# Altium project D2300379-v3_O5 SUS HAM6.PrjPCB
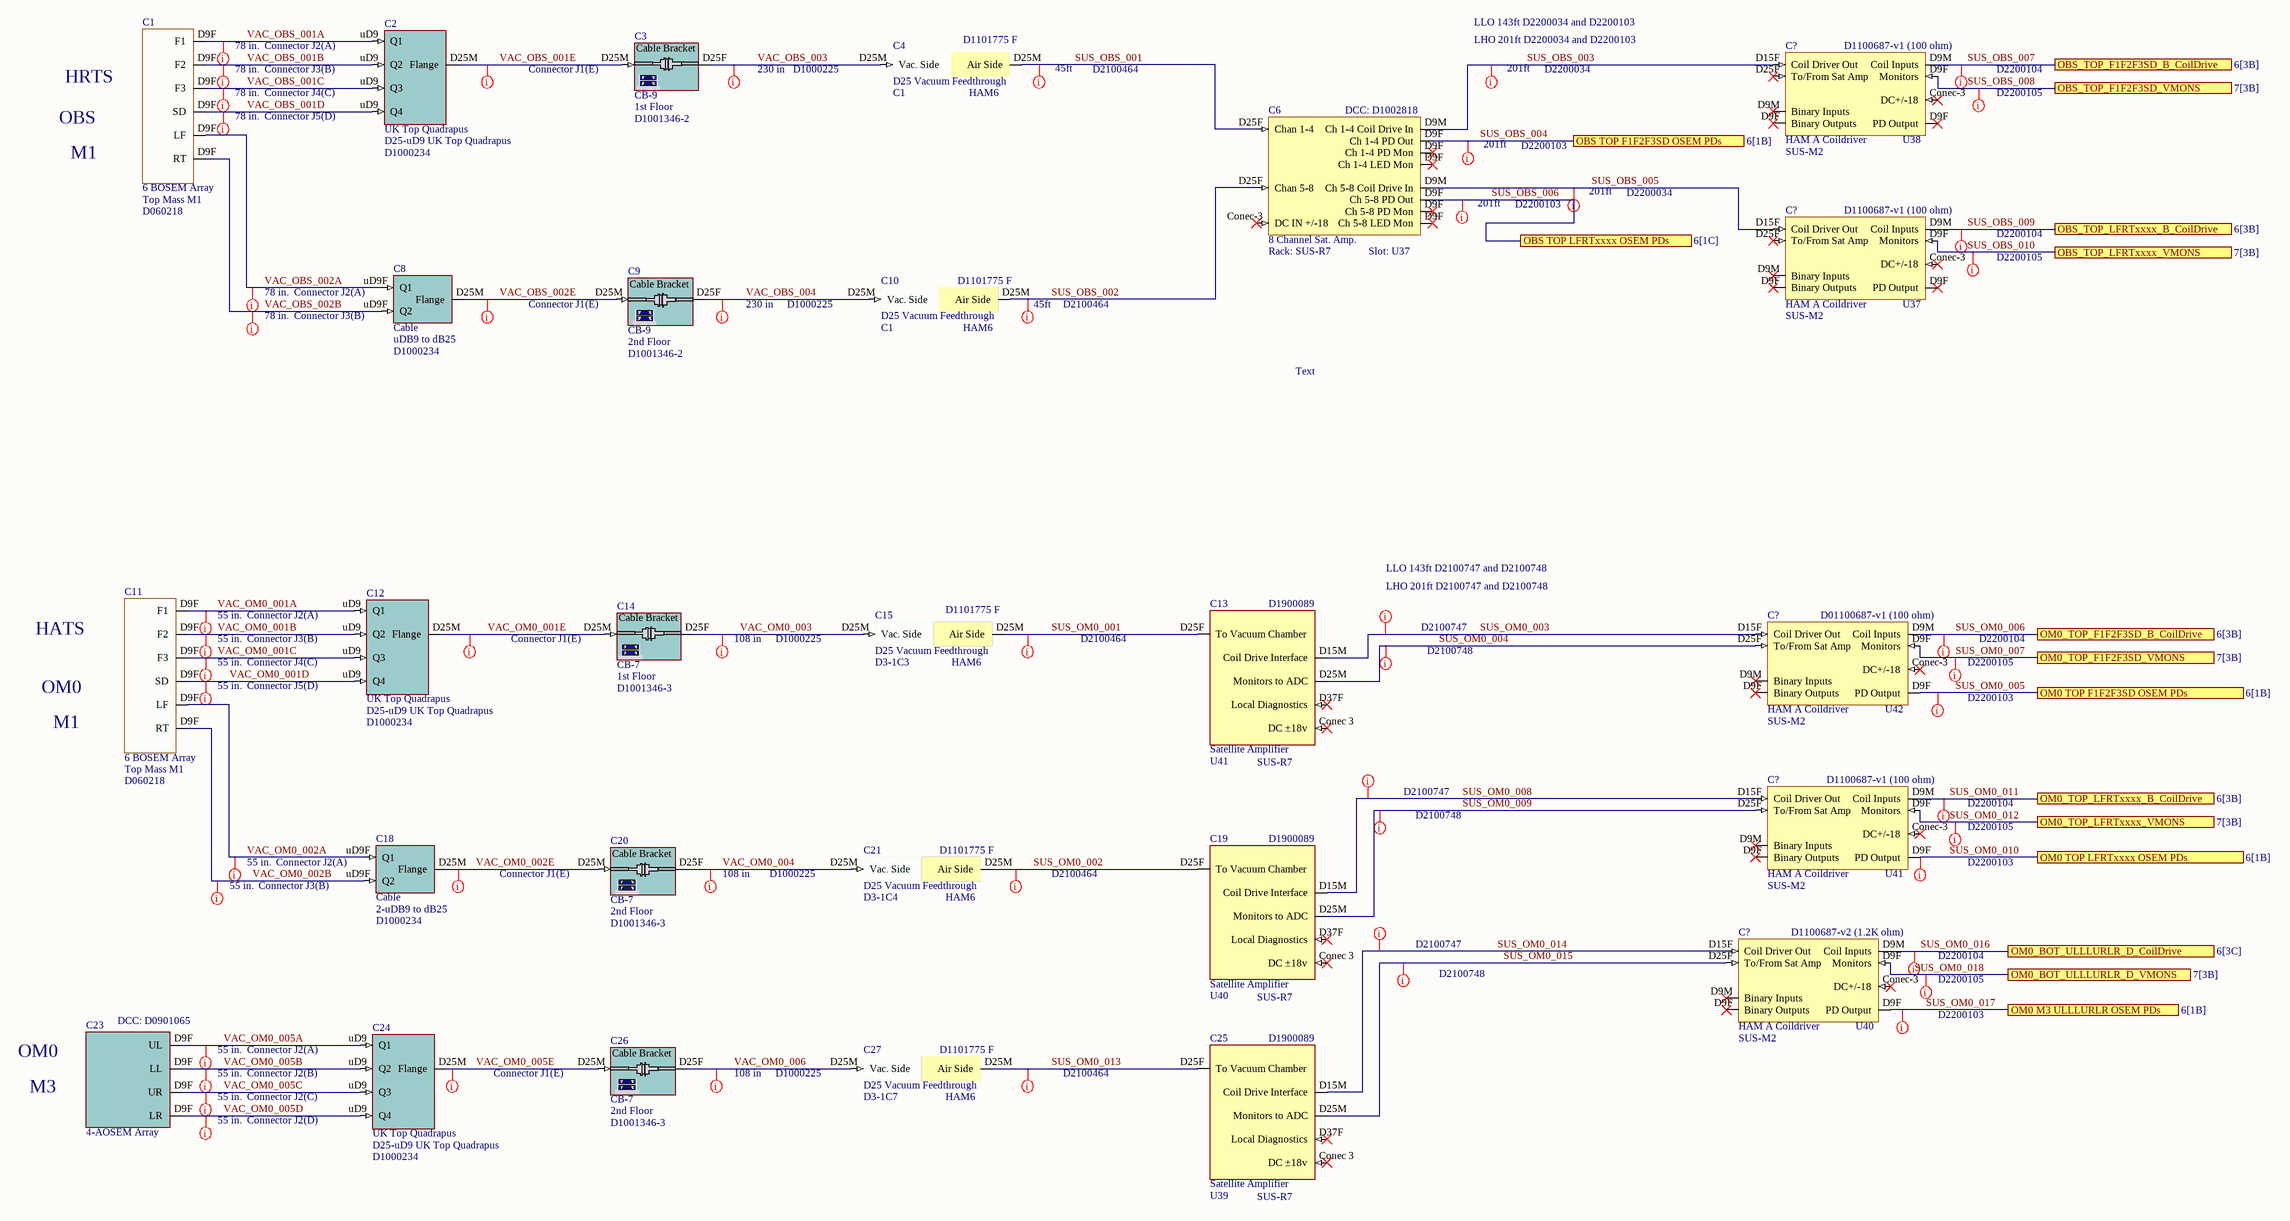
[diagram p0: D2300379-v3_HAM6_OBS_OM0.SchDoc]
5 sheets, 65 parts. Net scope: flat (ports and power ports of the same name join across sheets).
Sheets:
  D2300379-v3_HAM6_OBS_OM0.SchDoc
  D2300379-v3_HAM6_OMA1_OMB1.SchDoc
  D2300379-v1_SUS_HAM6_ADC_DAC.SchDoc
  D2300379-v1_SUSAUXH6_ADC_DAC.SchDoc
  D2300379-v1_RACK_SUS_R7.SchDoc

## Sheet D2300379-v3_HAM6_OBS_OM0.SchDoc: HAM6 OBS OM0
size C; Engineer: L. Sanchez; Organization: LIGO Laboratory; Address1: California Institute of Technology; Address2: Massachusetts Institute of Technology; DocumentNumber: D2300379; Revision: v2; SheetNumber: 1; SheetTotal: 9

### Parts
(Parts that share a designator on the sheet are numbered #1, #2 ... from top to bottom, then left to right.)
C1  6 BOSEM Array  Parameter: Top Mass M1  DCC: D060218
C2  UK Top Quadrapus  Parameter: D25-uD9 UK Top Quadrapus  DCC: D1000234
C3  Rack: CB-9  Slot: 1st Floor  DCC: D1001346-2  (hidden comment: Cable Bracket)
C4  D25 Vacuum Feedthrough  value C1  DCC: D1101775 F  Chamber: HAM6
C6  8 Channel Sat. Amp.  DCC: D1002818  Rack: SUS-R7  Slot: U37
C8  Cable  value uDB9 to dB25  DCC: D1000234
C9  Rack: CB-9  Slot: 2nd Floor  DCC: D1001346-2  (hidden comment: Cable Bracket)
C10  D25 Vacuum Feedthrough  value C1  DCC: D1101775 F  Chamber: HAM6
C11  6 BOSEM Array  Parameter: Top Mass M1  DCC: D060218
C12  UK Top Quadrapus  Parameter: D25-uD9 UK Top Quadrapus  DCC: D1000234
C13  Satellite Amplifier  Slot: U41  Rack: SUS-R7  DCC: D1900089
C14  Rack: CB-7  Slot: 1st Floor  DCC: D1001346-3  (hidden comment: Cable Bracket)
C15  D25 Vacuum Feedthrough  value D3-1C3  DCC: D1101775 F  Chamber: HAM6
C18  Cable  value 2-uDB9 to dB25  DCC: D1000234
C19  Satellite Amplifier  Slot: U40  Rack: SUS-R7  DCC: D1900089
C20  Rack: CB-7  Slot: 2nd Floor  DCC: D1001346-3  (hidden comment: Cable Bracket)
C21  D25 Vacuum Feedthrough  value D3-1C4  DCC: D1101775 F  Chamber: HAM6
C23  4-AOSEM Array  DCC: D0901065
C24  UK Top Quadrapus  Parameter: D25-uD9 UK Top Quadrapus  DCC: D1000234
C25  Satellite Amplifier  Slot: U39  Rack: SUS-R7  DCC: D1900089
C26  Rack: CB-7  Slot: 2nd Floor  DCC: D1001346-3  (hidden comment: Cable Bracket)
C27  D25 Vacuum Feedthrough  value D3-1C7  DCC: D1101775 F  Chamber: HAM6
C?#1  HAM A Coildriver
C?#2  HAM A Coildriver
C?#3  HAM A Coildriver
C?#4  HAM A Coildriver
C?#5  HAM A Coildriver

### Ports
OBS TOP F1F2F3SD OSEM PDs (see 6[1B]), OBS TOP LFRTxxxx OSEM PDs (see 6[1C]), OBS_TOP_F1F2F3SD_B_CoilDrive (see 6[3B]), OBS_TOP_F1F2F3SD_VMONS (see 7[3B]), OBS_TOP_LFRTxxxx_B_CoilDrive (see 6[3B]), OBS_TOP_LFRTxxxx_VMONS (see 7[3B]), OM0 M3 ULLLURLR OSEM PDs (see 6[1B]), OM0 TOP F1F2F3SD OSEM PDs (see 6[1B]), OM0 TOP LFRTxxxx OSEM PDs (see 6[1B]), OM0_BOT_ULLLURLR_D_CoilDrive (see 6[3C]), OM0_BOT_ULLLURLR_D_VMONS (see 7[3B]), OM0_TOP_F1F2F3SD_B_CoilDrive (see 6[3B]), OM0_TOP_F1F2F3SD_VMONS (see 7[3B]), OM0_TOP_LFRTxxxx_B_CoilDrive (see 6[3B]), OM0_TOP_LFRTxxxx_VMONS (see 7[3B])

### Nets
SUS_OBS_001: C4.D25M(Air_Side) C6.D25F(Chan_1-4)
SUS_OBS_002: C6.D25F(Chan_5-8) C10.D25M(Air_Side)
SUS_OBS_003: C6.D9M(Ch_1-4_Coil_Drive_In) C?#1.D15F(Coil_Driver_Out)
SUS_OBS_004: C6.D9F(Ch_1-4_PD_Out) ; port OBS TOP F1F2F3SD OSEM PDs
SUS_OBS_005: C6.D9M(Ch_5-8_Coil_Drive_In) C?#2.D15F(Coil_Driver_Out)
SUS_OBS_006: C6.D9F(Ch_5-8_PD_Out) ; port OBS TOP LFRTxxxx OSEM PDs
SUS_OBS_007: C?#1.D9M(Coil_Inputs) ; port OBS_TOP_F1F2F3SD_B_CoilDrive
SUS_OBS_008: C?#1.D9F(PD_Output) ; port OBS_TOP_F1F2F3SD_VMONS
SUS_OBS_009: C?#2.D9M(Coil_Inputs) ; port OBS_TOP_LFRTxxxx_B_CoilDrive
SUS_OBS_010: C?#2.D9F(PD_Output) ; port OBS_TOP_LFRTxxxx_VMONS
SUS_OM0_001: C13.D25F(To_Vacuum_Chamber) C15.D25M(Air_Side)
SUS_OM0_002: C19.D25F(To_Vacuum_Chamber) C21.D25M(Air_Side)
SUS_OM0_003: C13.D15M(Coil_Drive_Interface) C?#3.D15F(Coil_Driver_Out)
SUS_OM0_004: C13.D25M(Monitors_to_ADC) C?#3.D25F(To/From_Sat_Amp)
SUS_OM0_005: C?#3.D9F(PD_Output) ; port OM0 TOP F1F2F3SD OSEM PDs
SUS_OM0_006: C?#3.D9M(Coil_Inputs) ; port OM0_TOP_F1F2F3SD_B_CoilDrive
SUS_OM0_007: C?#3.D9F(Monitors) ; port OM0_TOP_F1F2F3SD_VMONS
SUS_OM0_008: C19.D15M(Coil_Drive_Interface) C?#4.D15F(Coil_Driver_Out)
SUS_OM0_009: C19.D25M(Monitors_to_ADC) C?#4.D25F(To/From_Sat_Amp)
SUS_OM0_010: C?#4.D9F(PD_Output) ; port OM0 TOP LFRTxxxx OSEM PDs
SUS_OM0_011: C?#4.D9M(Coil_Inputs) ; port OM0_TOP_LFRTxxxx_B_CoilDrive
SUS_OM0_012: C?#4.D9F(Monitors) ; port OM0_TOP_LFRTxxxx_VMONS
SUS_OM0_013: C25.D25F(To_Vacuum_Chamber) C27.D25M(Air_Side)
SUS_OM0_014: C25.D15M(Coil_Drive_Interface) C?#5.D15F(Coil_Driver_Out)
SUS_OM0_015: C25.D25M(Monitors_to_ADC) C?#5.D25F(To/From_Sat_Amp)
SUS_OM0_016: C?#5.D9M(Coil_Inputs) ; port OM0_BOT_ULLLURLR_D_CoilDrive
SUS_OM0_017: C?#5.D9F(PD_Output) ; port OM0 M3 ULLLURLR OSEM PDs
SUS_OM0_018: C?#5.D9F(Monitors) ; port OM0_BOT_ULLLURLR_D_VMONS
VAC_OBS_001A: C1.D9F(F1) C2.uD9(Q1)
VAC_OBS_001B: C1.D9F(F2) C2.uD9(Q2)
VAC_OBS_001C: C1.D9F(F3) C2.uD9(Q3)
VAC_OBS_001D: C1.D9F(SD) C2.uD9(Q4)
VAC_OBS_001E: C2.D25M(Flange) C3.D25M
VAC_OBS_002A: C1.D9F(LF) C8.uD9F(Q1)
VAC_OBS_002B: C1.D9F(RT) C8.uD9F(Q2)
VAC_OBS_002E: C8.D25M(Flange) C9.D25M
VAC_OBS_003: C3.D25F C4.D25M(Vac._Side)
VAC_OBS_004: C9.D25F C10.D25M(Vac._Side)
VAC_OM0_001A: C11.D9F(F1) C12.uD9(Q1)
VAC_OM0_001B: C11.D9F(F2) C12.uD9(Q2)
VAC_OM0_001C: C11.D9F(F3) C12.uD9(Q3)
VAC_OM0_001D: C11.D9F(SD) C12.uD9(Q4)
VAC_OM0_001E: C12.D25M(Flange) C14.D25M
VAC_OM0_002A: C11.D9F(LF) C18.uD9F(Q1)
VAC_OM0_002B: C11.D9F(RT) C18.uD9F(Q2)
VAC_OM0_002E: C18.D25M(Flange) C20.D25M
VAC_OM0_003: C14.D25F C15.D25M(Vac._Side)
VAC_OM0_004: C20.D25F C21.D25M(Vac._Side)
VAC_OM0_005A: C23.D9F(UL) C24.uD9(Q1)
VAC_OM0_005B: C23.D9F(LL) C24.uD9(Q2)
VAC_OM0_005C: C23.D9F(UR) C24.uD9(Q3)
VAC_OM0_005D: C23.D9F(LR) C24.uD9(Q4)
VAC_OM0_005E: C24.D25M(Flange) C26.D25M
VAC_OM0_006: C26.D25F C27.D25M(Vac._Side)

Not connected (* = marked no-connect by the designer): C6 Conec-3(DC_IN_+/-18)*; C13 Conec 3(DC_±18v)* D37F(Local_Diagnostics)*; C19 Conec 3(DC_±18v)* D37F(Local_Diagnostics)*; C25 Conec 3(DC_±18v)* D37F(Local_Diagnostics)*; C?#1 Conec-3(DC+/-18)* D25F(To/From_Sat_Amp)*; C?#2 Conec-3(DC+/-18)* D25F(To/From_Sat_Amp)*; C?#3 Conec-3(DC+/-18)*; C?#4 Conec-3(DC+/-18)*; C?#5 Conec-3(DC+/-18)*

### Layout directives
DCC: D2200103: SUS_OM0_005, SUS_OM0_010, SUS_OM0_017
DCC: D2100748: SUS_OM0_004, SUS_OM0_009, SUS_OM0_015
DCC: D2100747: SUS_OM0_003, SUS_OM0_008, SUS_OM0_014
Length: 201ft; DCC: D2200034: SUS_OBS_003, SUS_OBS_005
Length: 201ft; DCC: D2200103: SUS_OBS_004, SUS_OBS_006
DCC: D2200104: SUS_OBS_007, SUS_OBS_009, SUS_OM0_006, SUS_OM0_011, SUS_OM0_016
DCC: D2200105: SUS_OBS_008, SUS_OBS_010, SUS_OM0_007, SUS_OM0_012, SUS_OM0_018
DCC: D1000225: VAC_OBS_003, VAC_OBS_004, VAC_OM0_003, VAC_OM0_004, VAC_OM0_006
DCC: D2100464: SUS_OM0_001, SUS_OM0_002, SUS_OM0_013
Length: 45ft; DCC: D2100464: SUS_OBS_001, SUS_OBS_002
DCC: Connector J2(A): VAC_OBS_001A, VAC_OBS_002A, VAC_OM0_001A, VAC_OM0_002A, VAC_OM0_005A
DCC: Connector J2(B): VAC_OM0_005B
DCC: Connector J2(C): VAC_OM0_005C
DCC: Connector J2(D): VAC_OM0_005D
DCC: Connector J1(E): VAC_OM0_005E
Length: 2.3ft; DCC: Connector J1(E): VAC_OBS_001E, VAC_OBS_002E, VAC_OM0_001E, VAC_OM0_002E
DCC: Connector J3(B): VAC_OBS_001B, VAC_OBS_002B, VAC_OM0_001B, VAC_OM0_002B
DCC: Connector J5(D): VAC_OBS_001D, VAC_OM0_001D
DCC: Connector J4(C): VAC_OBS_001C, VAC_OM0_001C

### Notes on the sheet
- (near C1) 78 in.
- LLO 143ft D2200034 and D2200103
- LHO 201ft D2200034 and D2200103
- (near C?#1) D1100687-v1 (100 ohm)
- HRTS
- 230 in
- OBS
- M1
- (near C?#1) SUS-M2
- (near C?#1) U38
- (near C?#2) D1100687-v1 (100 ohm)
- 78 in.
- (near C?#2) SUS-M2
- (near C?#2) U37
- Text
- LLO 143ft D2100747 and D2100748
- HATS
- (near C11) 55 in.
- 108 in
- LHO 201ft D2100747 and D2100748
- (near C?#3) D01100687-v1 (100 ohm)
- OM0
- (near C?#3) SUS-M2
- (near C?#3) U42
- (near C?#4) D1100687-v1 (100 ohm)
- 55 in.
- (near C?#4) U41
- (near C?#4) SUS-M2
- (near C?#5) D1100687-v2 (1.2K ohm)
- (near C?#5) SUS-M2
- (near C?#5) U40
- M3

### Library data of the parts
C1 C11 = BOSEM_BS_M1: BOSEM; Serial: Sxxxxxxx; System: SUS; Rack: R?; Slot: U?
C2 C12 C24 = D1000234 D25 Quadrapus: Slot: U?; Rack: R?; Serial: Sxxxxxxx; System: SUS
C3 C14 = D1001347-2 1st Cable Bracket: D1001347-2 1/2 Cable Bracket for BSC Tables; Serial: Sxxxxxxx; System: SUS
C4 C10 C15 C21 C27 = VacFeedD25: Serial: Sxxxxxxx; System: ISC; Rack: R?; Slot: U?
C6 = 8 Channel Sat. Amp.: Serial: Sxxxxxxx; System: ISC
C8 C18 = D2100050 D25 2-udB9: Rack: SUS-R?; Serial: Sxxxxxxx; Slot: U?; System: SUS
C9 C20 C26 = D1001347-2 2nd Cable Bracket: D1001347-2 2/2 Cable Bracket for BSC Tables; Serial: Sxxxxxxx; System: SUS
C13 C19 C25 = Satellite Amplifier D1900089: System: SUS; Serial: Sxxxxxxx
C23 = 4-BOSEM Array: Rack: SUS-R?; Serial: Sxxxxxxx; Slot: U?; System: SUS; Parameter: OM3 HAM6 M1
C?#1-C?#5 = CD HAM-A D1100687: Serial: Sxxxxxxx; System: ISC

## Sheet D2300379-v3_HAM6_OMA1_OMB1.SchDoc: HAM6 OMA1,OMB1 DITHERS SUS
size C; Engineer: L. Sanchez; Organization: LIGO Laboratory; Address1: California Institute of Technology; Address2: Massachusetts Institute of Technology; DocumentNumber: D2300379; Revision: v2; SheetNumber: 2; SheetTotal: 9
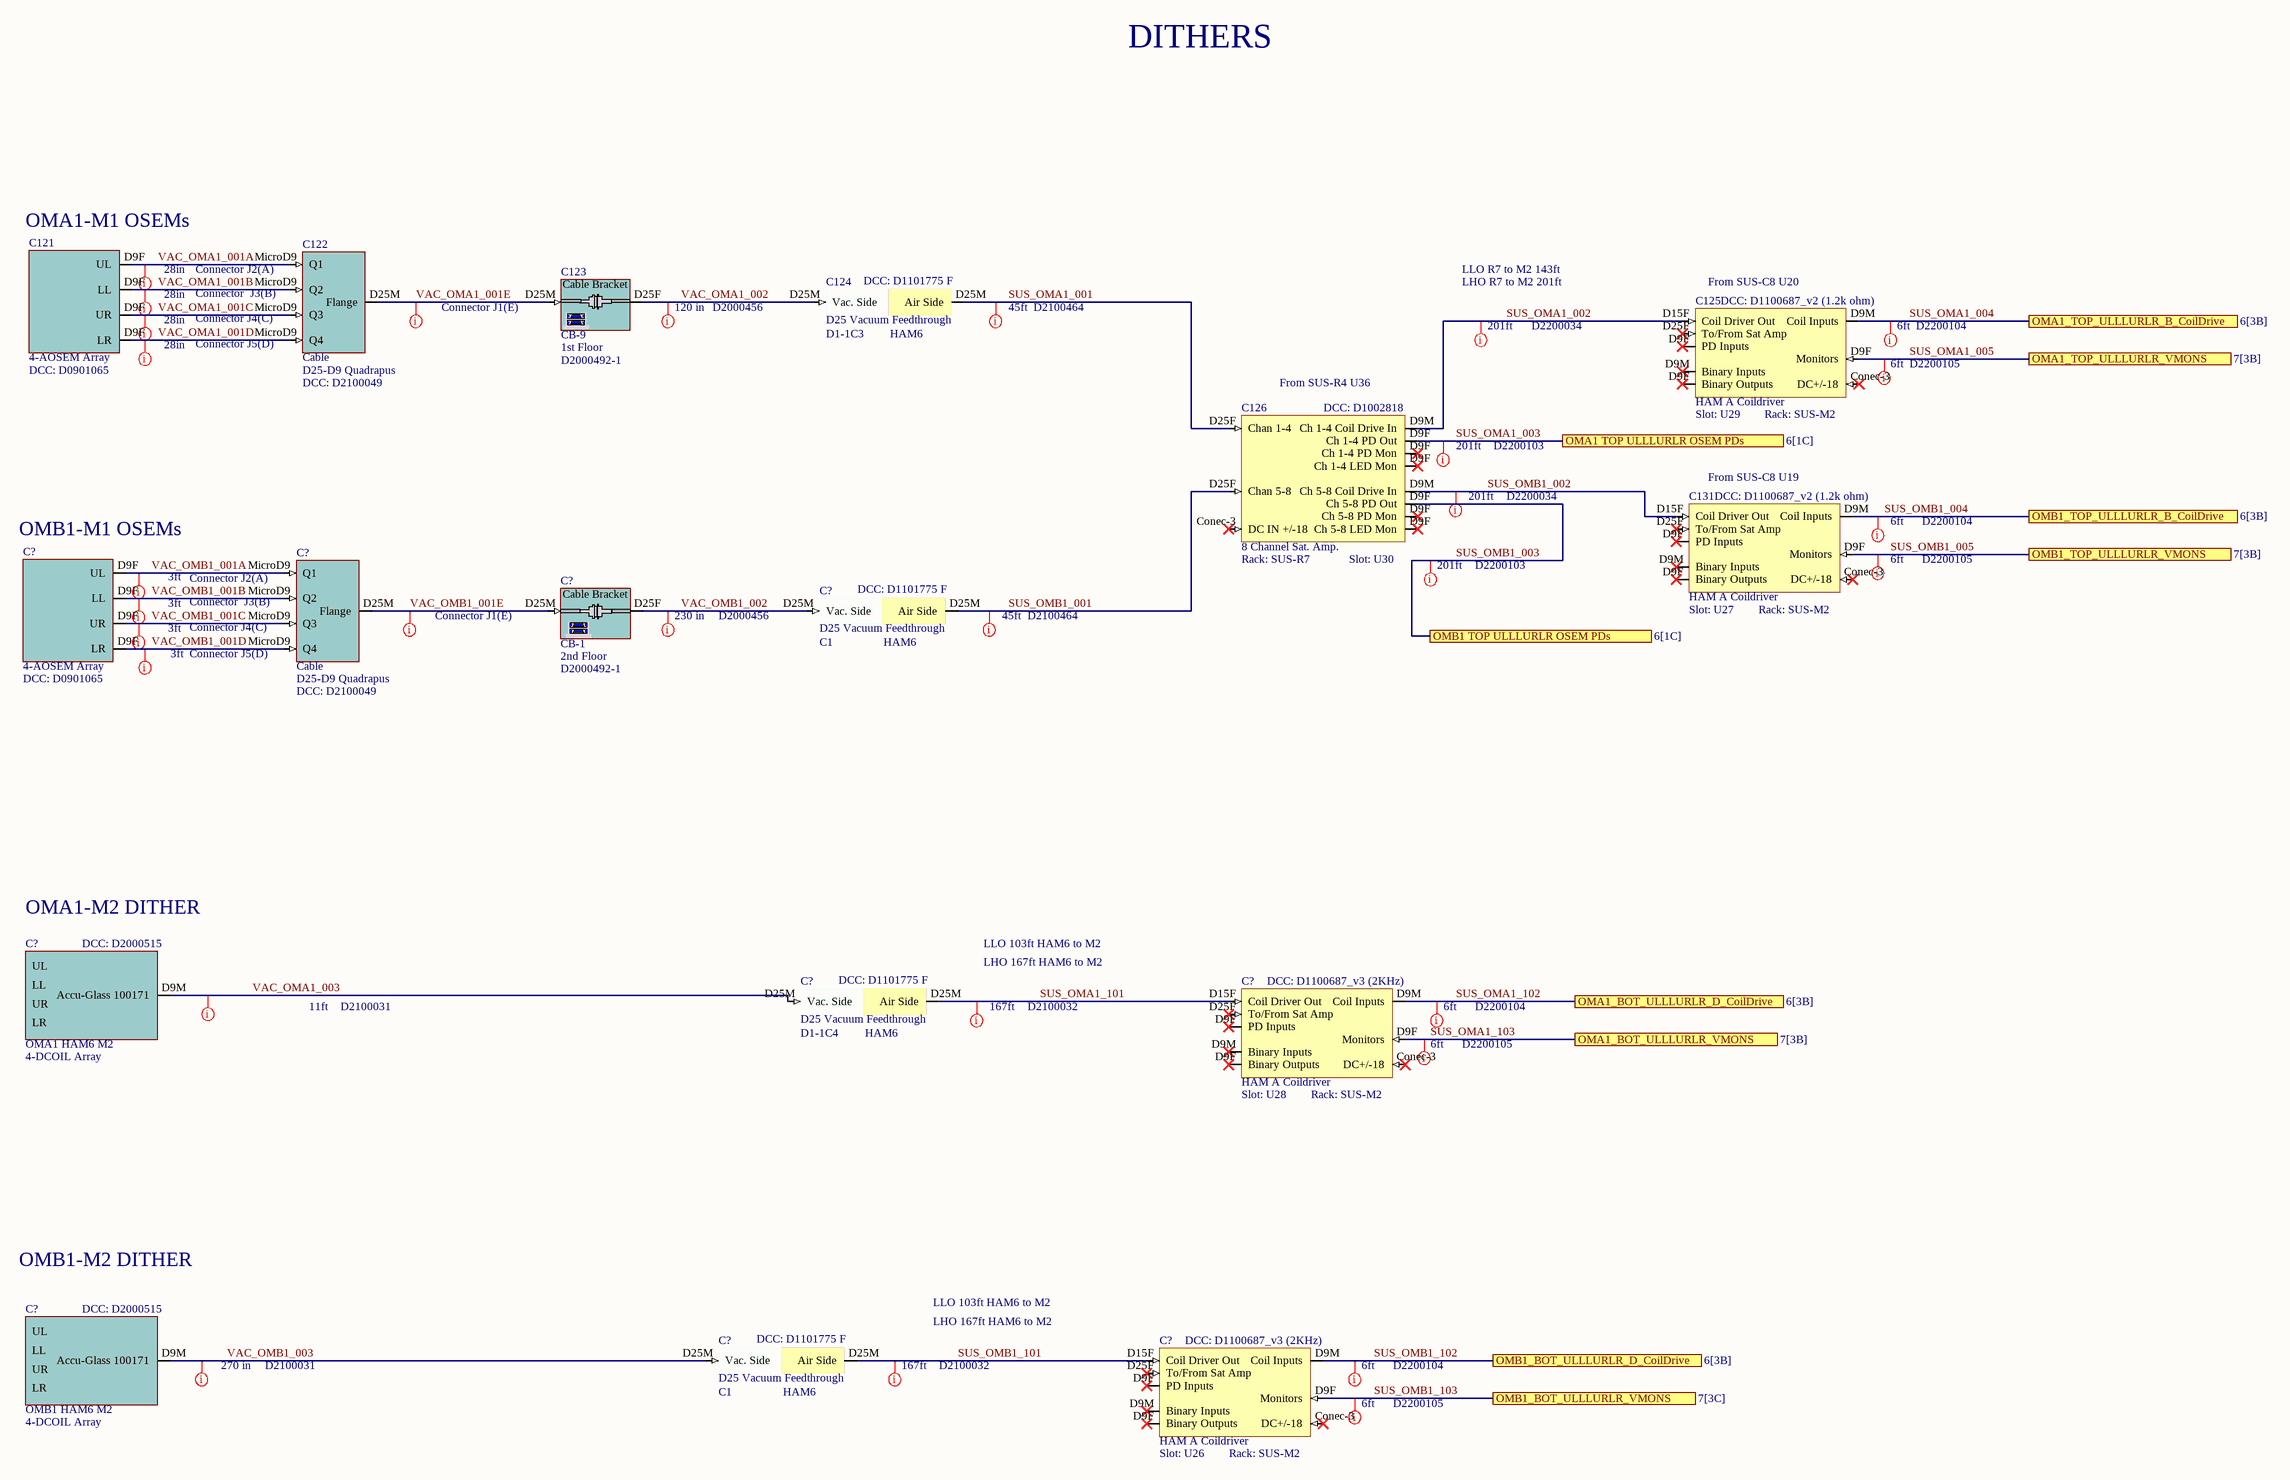
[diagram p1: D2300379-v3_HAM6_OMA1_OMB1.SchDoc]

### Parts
(Parts that share a designator on the sheet are numbered #1, #2 ... from top to bottom, then left to right.)
C121  4-AOSEM Array  DCC: D0901065
C122  Cable  value D25-D9 Quadrapus  DCC: D2100049
C123  Rack: CB-9  Slot: 1st Floor  DCC: D2000492-1  (hidden comment: Cable Bracket)
C124  D25 Vacuum Feedthrough  DCC: D1101775 F  Feedthrough: D1-1C3  Chamber: HAM6
C125  HAM A Coildriver  DCC: D1100687_v2 (1.2k ohm)  Rack: SUS-M2  Slot: U29
C126  8 Channel Sat. Amp.  DCC: D1002818  Rack: SUS-R7  Slot: U30
C131  HAM A Coildriver  DCC: D1100687_v2 (1.2k ohm)  Rack: SUS-M2  Slot: U27
C?#6  Rack: CB-1  Slot: 2nd Floor  DCC: D2000492-1  (hidden comment: Cable Bracket)
C?#7  D25 Vacuum Feedthrough  DCC: D1101775 F  Feedthrough: C1  Chamber: HAM6
C?#8  4-AOSEM Array  DCC: D0901065
C?#9  Cable  value D25-D9 Quadrapus  DCC: D2100049
C?#10  value 4-DCOIL Array  Rack: OMA1 HAM6 M2  DCC: D2000515  (hidden comment: Cable)
C?#11  D25 Vacuum Feedthrough  DCC: D1101775 F  Feedthrough: D1-1C4  Chamber: HAM6
C?#12  HAM A Coildriver  DCC: D1100687_v3 (2KHz)  Rack: SUS-M2  Slot: U28
C?#13  value 4-DCOIL Array  Rack: OMB1 HAM6 M2  DCC: D2000515  (hidden comment: Cable)
C?#14  D25 Vacuum Feedthrough  DCC: D1101775 F  Feedthrough: C1  Chamber: HAM6
C?#15  HAM A Coildriver  DCC: D1100687_v3 (2KHz)  Rack: SUS-M2  Slot: U26

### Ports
OMA1 TOP ULLLURLR OSEM PDs (see 6[1C]), OMA1_BOT_ULLLURLR_D_CoilDrive (see 6[3B]), OMA1_BOT_ULLLURLR_VMONS (see 7[3B]), OMA1_TOP_ULLLURLR_B_CoilDrive (see 6[3B]), OMA1_TOP_ULLLURLR_VMONS (see 7[3B]), OMB1 TOP ULLLURLR OSEM PDs (see 6[1C]), OMB1_BOT_ULLLURLR_D_CoilDrive (see 6[3B]), OMB1_BOT_ULLLURLR_VMONS (see 7[3C]), OMB1_TOP_ULLLURLR_B_CoilDrive (see 6[3B]), OMB1_TOP_ULLLURLR_VMONS (see 7[3B])

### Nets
SUS_OMA1_001: C124.D25M(Air_Side) C126.D25F(Chan_1-4)
SUS_OMA1_002: C125.D15F(Coil_Driver_Out) C126.D9M(Ch_1-4_Coil_Drive_In)
SUS_OMA1_003: C126.D9F(Ch_1-4_PD_Out) ; port OMA1 TOP ULLLURLR OSEM PDs
SUS_OMA1_004: C125.D9M(Coil_Inputs) ; port OMA1_TOP_ULLLURLR_B_CoilDrive
SUS_OMA1_005: C125.D9F(PD_Inputs) ; port OMA1_TOP_ULLLURLR_VMONS
SUS_OMA1_101: C?#11.D25M(Air_Side) C?#12.D15F(Coil_Driver_Out)
SUS_OMA1_102: C?#12.D9M(Coil_Inputs) ; port OMA1_BOT_ULLLURLR_D_CoilDrive
SUS_OMA1_103: C?#12.D9F(PD_Inputs) ; port OMA1_BOT_ULLLURLR_VMONS
SUS_OMB1_001: C126.D25F(Chan_5-8) C?#7.D25M(Air_Side)
SUS_OMB1_002: C126.D9M(Ch_5-8_Coil_Drive_In) C131.D15F(Coil_Driver_Out)
SUS_OMB1_003: C126.D9F(Ch_5-8_PD_Out) ; port OMB1 TOP ULLLURLR OSEM PDs
SUS_OMB1_004: C131.D9M(Coil_Inputs) ; port OMB1_TOP_ULLLURLR_B_CoilDrive
SUS_OMB1_005: C131.D9F(PD_Inputs) ; port OMB1_TOP_ULLLURLR_VMONS
SUS_OMB1_101: C?#14.D25M(Air_Side) C?#15.D15F(Coil_Driver_Out)
SUS_OMB1_102: C?#15.D9M(Coil_Inputs) ; port OMB1_BOT_ULLLURLR_D_CoilDrive
SUS_OMB1_103: C?#15.D9F(PD_Inputs) ; port OMB1_BOT_ULLLURLR_VMONS
VAC_OMA1_001A: C121.D9F(UL) C122.MicroD9(Q1)
VAC_OMA1_001B: C121.D9F(LL) C122.MicroD9(Q2)
VAC_OMA1_001C: C121.D9F(UR) C122.MicroD9(Q3)
VAC_OMA1_001D: C121.D9F(LR) C122.MicroD9(Q4)
VAC_OMA1_001E: C122.D25M(Flange) C123.D25M
VAC_OMA1_002: C123.D25F C124.D25M(Vac._Side)
VAC_OMA1_003: C?#10.D9M(Accu-Glass_100171) C?#11.D25M(Vac._Side)
VAC_OMB1_001A: C?#8.D9F(UL) C?#9.MicroD9(Q1)
VAC_OMB1_001B: C?#8.D9F(LL) C?#9.MicroD9(Q2)
VAC_OMB1_001C: C?#8.D9F(UR) C?#9.MicroD9(Q3)
VAC_OMB1_001D: C?#8.D9F(LR) C?#9.MicroD9(Q4)
VAC_OMB1_001E: C?#6.D25M C?#9.D25M(Flange)
VAC_OMB1_002: C?#6.D25F C?#7.D25M(Vac._Side)
VAC_OMB1_003: C?#13.D9M(Accu-Glass_100171) C?#14.D25M(Vac._Side)

Not connected (* = marked no-connect by the designer): C125 Conec-3(DC+/-18)* D25F(To/From_Sat_Amp)*; C126 Conec-3(DC_IN_+/-18)*; C131 Conec-3(DC+/-18)* D25F(To/From_Sat_Amp)*; C?#12 Conec-3(DC+/-18)* D25F(To/From_Sat_Amp)*; C?#15 Conec-3(DC+/-18)* D25F(To/From_Sat_Amp)*

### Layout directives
Length: 28in; DCC: Connector J2(A): VAC_OMA1_001A
Length: 28in; DCC: Connector  J3(B): VAC_OMA1_001B
Length: 28in; DCC: Connector J4(C): VAC_OMA1_001C
Length: 201ft; DCC: D2200034: SUS_OMA1_002, SUS_OMB1_002
Length: 201ft; DCC: D2200103: SUS_OMA1_003, SUS_OMB1_003
Length: 5; DCC: Connector J1(E): VAC_OMA1_001E, VAC_OMB1_001E
Length: 120 in; DCC: D2000456: VAC_OMA1_002
Length: 6ft; DCC: D2200104: SUS_OMA1_004, SUS_OMA1_102, SUS_OMB1_004, SUS_OMB1_102
Length: 6ft; DCC: D2200105: SUS_OMA1_005, SUS_OMA1_103, SUS_OMB1_005, SUS_OMB1_103
Length: 45ft; DCC: D2100464: SUS_OMA1_001, SUS_OMB1_001
Length: 28in; DCC: Connector J5(D): VAC_OMA1_001D
Length: 167ft; DCC: D2100032: SUS_OMA1_101, SUS_OMB1_101
Length: 11ft; DCC: D2100031: VAC_OMA1_003
Length: 270 in; DCC: D2100031: VAC_OMB1_003
Length: 3ft; DCC: Connector J5(D): VAC_OMB1_001D
Length: 3ft; DCC: Connector J2(A): VAC_OMB1_001A
Length: 3ft; DCC: Connector  J3(B): VAC_OMB1_001B
Length: 3ft; DCC: Connector J4(C): VAC_OMB1_001C
Length: 230 in; DCC: D2000456: VAC_OMB1_002

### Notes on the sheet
- DITHERS
- (near C121) OMA1-M1 OSEMs
- LLO R7 to M2 143ft
- LHO R7 to M2 201ft
- (near C125) From SUS-C8 U20
- (near C126) From SUS-R4 U36
- (near C131) From SUS-C8 U19
- (near C?#8) OMB1-M1 OSEMs
- OMA1-M2 DITHER
- LLO 103ft HAM6 to M2
- LHO 167ft HAM6 to M2
- OMB1-M2 DITHER

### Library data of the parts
C121 = 4-BOSEM Array: Rack: SUS-R?; Serial: Sxxxxxxx; Slot: U?; System: SUS; Parameter: OMA1 HAM6 M1
C122 C?#9 = Flange: Rack: SUS-R?; Serial: Sxxxxxxx; Slot: U?; System: SUS
C123 = D1001347-2 1st Cable Bracket: as C3 on sheet D2300379-v3_HAM6_OBS_OM0
C124 C?#7 C?#11 C?#14 = VacFeedD25: as C4 on sheet D2300379-v3_HAM6_OBS_OM0
C125 C131 C?#12 C?#15 = HAM A Coildriver: Serial: Sxxxxxxx; System: ISC
C126 = 8 Channel Sat. Amp.: Serial: Sxxxxxxx; System: ISC
C?#6 = D1001347-2 2nd Cable Bracket: as C9 on sheet D2300379-v3_HAM6_OBS_OM0
C?#8 = 4-BOSEM Array: Rack: SUS-R?; Serial: Sxxxxxxx; Slot: U?; System: SUS; Parameter: OMB1 HAM6 M1
C?#10 C?#13 = COSEM Array: Serial: Sxxxxxxx; Slot: U?; System: SUS

## Sheet D2300379-v1_SUS_HAM6_ADC_DAC.SchDoc: SUS HAM6 Controls IO Chains
size C; Engineer: L. Sanchez; Organization: LIGO Laboratory; Address1: California Institute of Technology; Address2: Massachusetts Institute of Technology; DocumentNumber: D2300379; Revision: v1; SheetNumber: 6; SheetTotal: 9
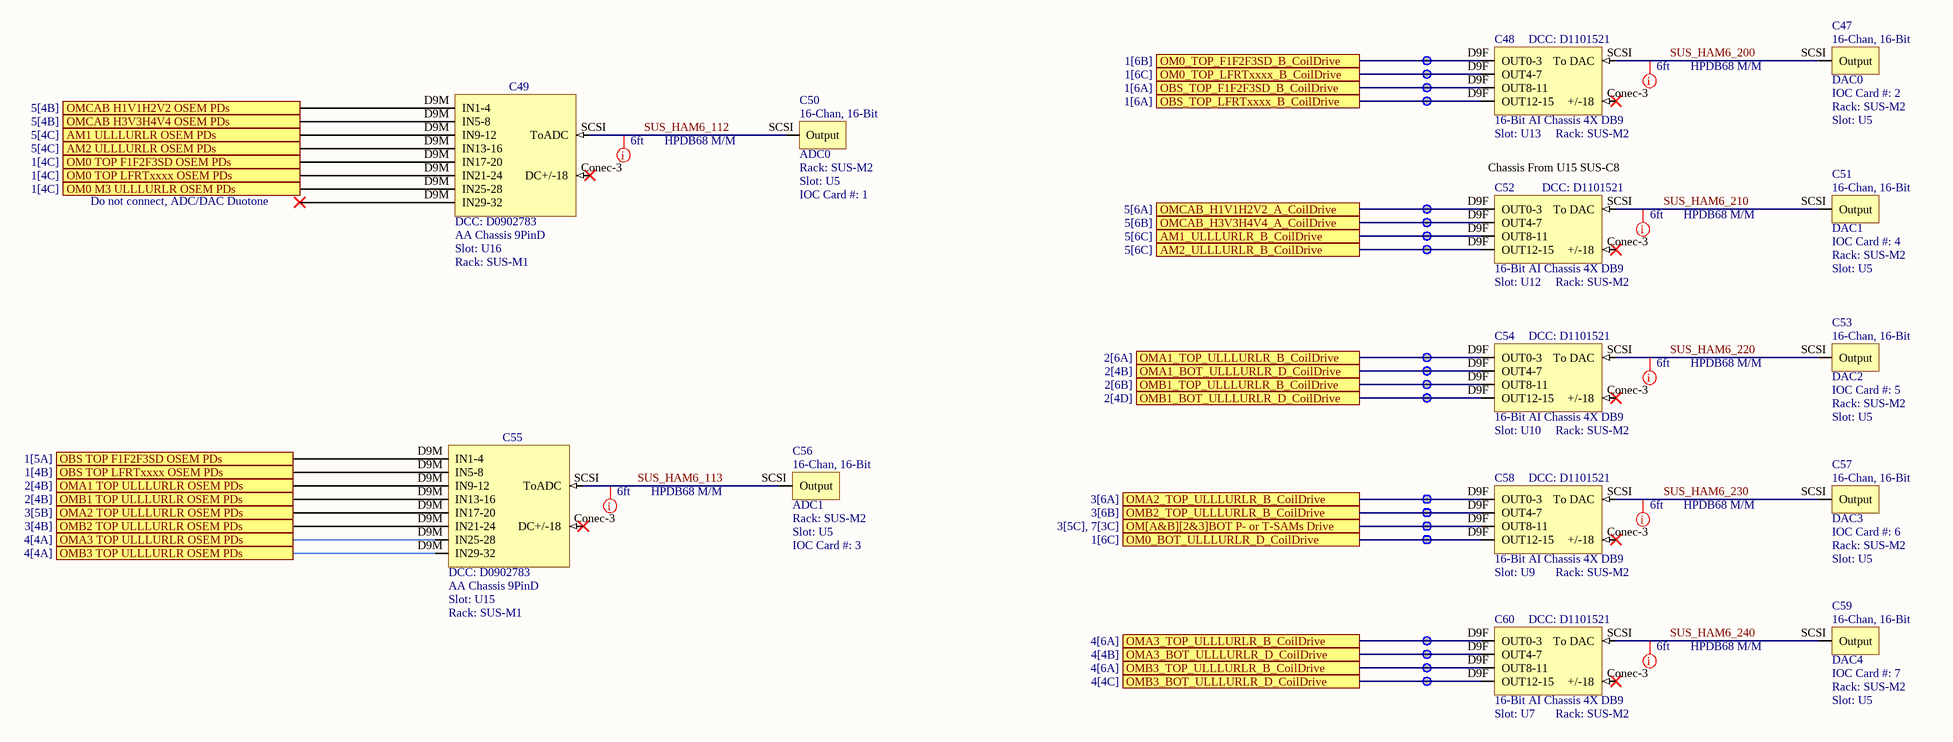
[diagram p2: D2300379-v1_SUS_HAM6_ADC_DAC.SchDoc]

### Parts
C47  DAC0  IOC Card #: 2  Rack: SUS-M2  Slot: U5
C48  16-Bit AI Chassis 4X DB9  DCC: D1101521  Rack: SUS-M2  Slot: U13
C49  AA Chassis 9PinD  DCC: D0902783  Rack: SUS-M1  Slot: U16
C50  ADC0  Rack: SUS-M2  Slot: U5  IOC Card #: 1
C51  DAC1  IOC Card #: 4  Rack: SUS-M2  Slot: U5
C52  16-Bit AI Chassis 4X DB9  DCC: D1101521  Rack: SUS-M2  Slot: U12
C53  DAC2  IOC Card #: 5  Rack: SUS-M2  Slot: U5
C54  16-Bit AI Chassis 4X DB9  DCC: D1101521  Rack: SUS-M2  Slot: U10
C55  AA Chassis 9PinD  DCC: D0902783  Rack: SUS-M1  Slot: U15
C56  ADC1  Rack: SUS-M2  Slot: U5  IOC Card #: 3
C57  DAC3  IOC Card #: 6  Rack: SUS-M2  Slot: U5
C58  16-Bit AI Chassis 4X DB9  DCC: D1101521  Rack: SUS-M2  Slot: U9
C59  DAC4  IOC Card #: 7  Rack: SUS-M2  Slot: U5
C60  16-Bit AI Chassis 4X DB9  DCC: D1101521  Rack: SUS-M2  Slot: U7

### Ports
AM1 ULLLURLR OSEM PDs (see 5[4C]), AM1_ULLLURLR_B_CoilDrive (see 5[6C]), AM2 ULLLURLR OSEM PDs (see 5[4C]), AM2_ULLLURLR_B_CoilDrive (see 5[6C]), OBS TOP F1F2F3SD OSEM PDs (see 1[5A]), OBS TOP LFRTxxxx OSEM PDs (see 1[4B]), OBS_TOP_F1F2F3SD_B_CoilDrive (see 1[6A]), OBS_TOP_LFRTxxxx_B_CoilDrive (see 1[6A]), OM0 M3 ULLLURLR OSEM PDs (see 1[4C]), OM0 TOP F1F2F3SD OSEM PDs (see 1[4C]), OM0 TOP LFRTxxxx OSEM PDs (see 1[4C]), OM0_BOT_ULLLURLR_D_CoilDrive (see 1[6C]), OM0_TOP_F1F2F3SD_B_CoilDrive (see 1[6B]), OM0_TOP_LFRTxxxx_B_CoilDrive (see 1[6C]), OM[A&B][2&3]BOT P- or T-SAMs Drive (see 3[5C], 7[3C]), OMA1 TOP ULLLURLR OSEM PDs (see 2[4B]), OMA1_BOT_ULLLURLR_D_CoilDrive (see 2[4B]), OMA1_TOP_ULLLURLR_B_CoilDrive (see 2[6A]), OMA2 TOP ULLLURLR OSEM PDs (see 3[5B]), OMA2_TOP_ULLLURLR_B_CoilDrive (see 3[6A]), OMA3 TOP ULLLURLR OSEM PDs (see 4[4A]), OMA3_BOT_ULLLURLR_D_CoilDrive (see 4[4B]), OMA3_TOP_ULLLURLR_B_CoilDrive (see 4[6A]), OMB1 TOP ULLLURLR OSEM PDs (see 2[4B]), OMB1_BOT_ULLLURLR_D_CoilDrive (see 2[4D]), OMB1_TOP_ULLLURLR_B_CoilDrive (see 2[6B]), OMB2 TOP ULLLURLR OSEM PDs (see 3[4B]), OMB2_TOP_ULLLURLR_B_CoilDrive (see 3[6B]), OMB3 TOP ULLLURLR OSEM PDs (see 4[4A]), OMB3_BOT_ULLLURLR_D_CoilDrive (see 4[4C]), OMB3_TOP_ULLLURLR_B_CoilDrive (see 4[6A]), OMCAB H1V1H2V2 OSEM PDs (see 5[4B]), OMCAB H3V3H4V4 OSEM PDs (see 5[4B]), OMCAB_H1V1H2V2_A_CoilDrive (see 5[6A]), OMCAB_H3V3H4V4_A_CoilDrive (see 5[6B])

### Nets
SUS_HAM6_112: C49.SCSI(ToADC) C50.SCSI(Output)
SUS_HAM6_113: C55.SCSI(ToADC) C56.SCSI(Output)
SUS_HAM6_200: C47.SCSI(Output) C48.SCSI(To_DAC)
SUS_HAM6_210: C51.SCSI(Output) C52.SCSI(To_DAC)
SUS_HAM6_220: C53.SCSI(Output) C54.SCSI(To_DAC)
SUS_HAM6_230: C57.SCSI(Output) C58.SCSI(To_DAC)
SUS_HAM6_240: C59.SCSI(Output) C60.SCSI(To_DAC)
SUS_OBS_004: C55.D9M(IN1-4) ; port OBS TOP F1F2F3SD OSEM PDs
SUS_OBS_006: C55.D9M(IN5-8) ; port OBS TOP LFRTxxxx OSEM PDs
SUS_OBS_007: C48.D9F(OUT8-11) ; port OBS_TOP_F1F2F3SD_B_CoilDrive
SUS_OBS_009: C48.D9F(OUT12-15) ; port OBS_TOP_LFRTxxxx_B_CoilDrive
SUS_OM0_005: C49.D9M(IN17-20) ; port OM0 TOP F1F2F3SD OSEM PDs
SUS_OM0_006: C48.D9F(OUT0-3) ; port OM0_TOP_F1F2F3SD_B_CoilDrive
SUS_OM0_010: C49.D9M(IN21-24) ; port OM0 TOP LFRTxxxx OSEM PDs
SUS_OM0_011: C48.D9F(OUT4-7) ; port OM0_TOP_LFRTxxxx_B_CoilDrive
SUS_OM0_016: C58.D9F(OUT12-15) ; port OM0_BOT_ULLLURLR_D_CoilDrive
SUS_OM0_017: C49.D9M(IN25-28) ; port OM0 M3 ULLLURLR OSEM PDs
SUS_OMA1_003: C55.D9M(IN9-12) ; port OMA1 TOP ULLLURLR OSEM PDs
SUS_OMA1_004: C54.D9F(OUT0-3) ; port OMA1_TOP_ULLLURLR_B_CoilDrive
SUS_OMA1_102: C54.D9F(OUT4-7) ; port OMA1_BOT_ULLLURLR_D_CoilDrive
SUS_OMB1_003: C55.D9M(IN13-16) ; port OMB1 TOP ULLLURLR OSEM PDs
SUS_OMB1_004: C54.D9F(OUT8-11) ; port OMB1_TOP_ULLLURLR_B_CoilDrive
SUS_OMB1_102: C54.D9F(OUT12-15) ; port OMB1_BOT_ULLLURLR_D_CoilDrive
NetC49_D9M: C49.D9M(IN1-4) ; port OMCAB H1V1H2V2 OSEM PDs
NetC49_D9M: C49.D9M(IN5-8) ; port OMCAB H3V3H4V4 OSEM PDs  [a separate net that carries the same name]
NetC49_D9M: C49.D9M(IN9-12) ; port AM1 ULLLURLR OSEM PDs  [a separate net that carries the same name]
NetC49_D9M: C49.D9M(IN13-16) ; port AM2 ULLLURLR OSEM PDs  [a separate net that carries the same name]
NetC52_D9F: C52.D9F(OUT0-3) ; port OMCAB_H1V1H2V2_A_CoilDrive
NetC52_D9F: C52.D9F(OUT4-7) ; port OMCAB_H3V3H4V4_A_CoilDrive  [a separate net that carries the same name]
NetC52_D9F: C52.D9F(OUT8-11) ; port AM1_ULLLURLR_B_CoilDrive  [a separate net that carries the same name]
NetC52_D9F: C52.D9F(OUT12-15) ; port AM2_ULLLURLR_B_CoilDrive  [a separate net that carries the same name]
NetC55_D9M: C55.D9M(IN17-20) ; port OMA2 TOP ULLLURLR OSEM PDs
NetC55_D9M: C55.D9M(IN21-24) ; port OMB2 TOP ULLLURLR OSEM PDs  [a separate net that carries the same name]
NetC55_D9M: C55.D9M(IN25-28) ; port OMA3 TOP ULLLURLR OSEM PDs  [a separate net that carries the same name]
NetC55_D9M: C55.D9M(IN29-32) ; port OMB3 TOP ULLLURLR OSEM PDs  [a separate net that carries the same name]
NetC58_D9F: C58.D9F(OUT0-3) ; port OMA2_TOP_ULLLURLR_B_CoilDrive
NetC58_D9F: C58.D9F(OUT4-7) ; port OMB2_TOP_ULLLURLR_B_CoilDrive  [a separate net that carries the same name]
NetC58_D9F: C58.D9F(OUT8-11) ; port OM[A&B][2&3]BOT P- or T-SAMs Drive  [a separate net that carries the same name]
NetC60_D9F: C60.D9F(OUT0-3) ; port OMA3_TOP_ULLLURLR_B_CoilDrive
NetC60_D9F: C60.D9F(OUT4-7) ; port OMA3_BOT_ULLLURLR_D_CoilDrive  [a separate net that carries the same name]
NetC60_D9F: C60.D9F(OUT8-11) ; port OMB3_TOP_ULLLURLR_B_CoilDrive  [a separate net that carries the same name]
NetC60_D9F: C60.D9F(OUT12-15) ; port OMB3_BOT_ULLLURLR_D_CoilDrive  [a separate net that carries the same name]

Not connected (* = marked no-connect by the designer): C48 Conec-3(+/-18)*; C49 Conec-3(DC+/-18)*; C52 Conec-3(+/-18)*; C54 Conec-3(+/-18)*; C55 Conec-3(DC+/-18)*; C58 Conec-3(+/-18)*; C60 Conec-3(+/-18)*

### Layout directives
Length: 6ft; DCC: HPDB68 M/M: SUS_HAM6_112, SUS_HAM6_113, SUS_HAM6_200, SUS_HAM6_210, SUS_HAM6_220, SUS_HAM6_230, SUS_HAM6_240

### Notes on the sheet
- Do not connect, ADC/DAC Duotone
- (near C52) Chassis From U15 SUS-C8

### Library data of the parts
C47 C51 C53 C57 C59 = DAC-16: 16 Chan, 16 Bit DAC
C48 C52 C54 C58 C60 = AI_9pin_16_bit: AI Chassis 4X DB9 16-bit; Serial: Sxxxxxxx; System: ISC
C49 C55 = AA_9pinAll: ISC AA Chassis 9PinD; Serial: Sxxxxxxx
C50 C56 = ADC-16: 16 Chan, 16 Bit ADC

## Sheet D2300379-v1_SUSAUXH6_ADC_DAC.SchDoc: SUS AUX HAM6 Coil Mon. IO Chains
size B; Engineer: L. Sanchez; Organization: LIGO Laboratory; Address1: California Institute of Technology; Address2: Massachusetts Institute of Technology; DocumentNumber: D2300379; Revision: v1; SheetNumber: 7; SheetTotal: 9
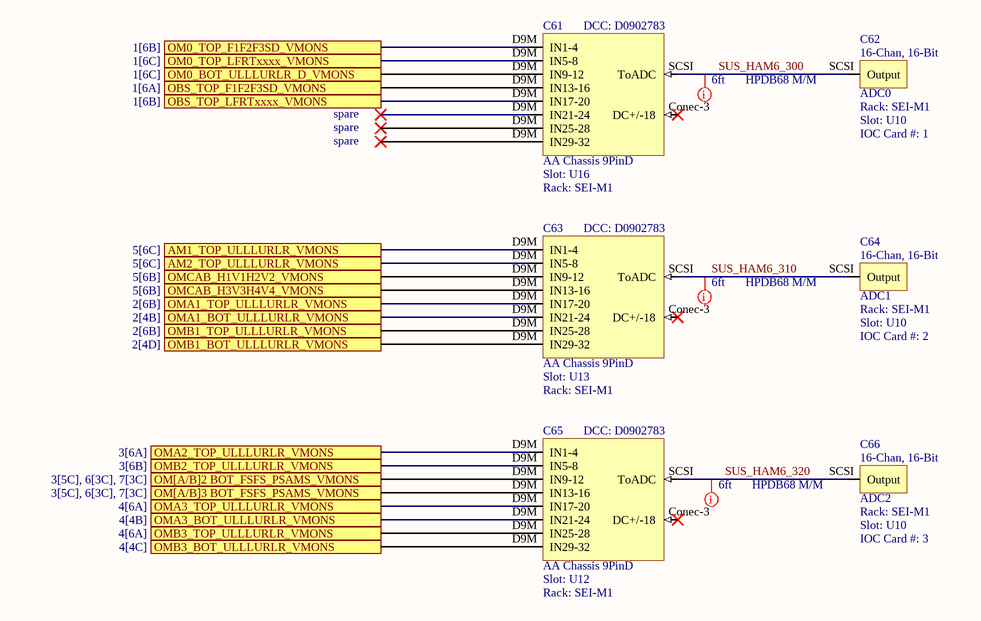
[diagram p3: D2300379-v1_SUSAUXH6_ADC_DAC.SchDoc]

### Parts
C61  AA Chassis 9PinD  Slot: U16  Rack: SEI-M1  DCC: D0902783
C62  ADC0  Rack: SEI-M1  Slot: U10  IOC Card #: 1
C63  AA Chassis 9PinD  Slot: U13  Rack: SEI-M1  DCC: D0902783
C64  ADC1  Rack: SEI-M1  Slot: U10  IOC Card #: 2
C65  AA Chassis 9PinD  Slot: U12  Rack: SEI-M1  DCC: D0902783
C66  ADC2  Rack: SEI-M1  Slot: U10  IOC Card #: 3

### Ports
AM1_TOP_ULLLURLR_VMONS (see 5[6C]), AM2_TOP_ULLLURLR_VMONS (see 5[6C]), OBS_TOP_F1F2F3SD_VMONS (see 1[6A]), OBS_TOP_LFRTxxxx_VMONS (see 1[6B]), OM0_BOT_ULLLURLR_D_VMONS (see 1[6C]), OM0_TOP_F1F2F3SD_VMONS (see 1[6B]), OM0_TOP_LFRTxxxx_VMONS (see 1[6C]), OM[A/B]2 BOT_FSFS_PSAMS_VMONS (see 3[5C], 6[3C], 7[3C]), OM[A/B]3 BOT_FSFS_PSAMS_VMONS (see 3[5C], 6[3C], 7[3C]), OMA1_BOT_ULLLURLR_VMONS (see 2[4B]), OMA1_TOP_ULLLURLR_VMONS (see 2[6B]), OMA2_TOP_ULLLURLR_VMONS (see 3[6A]), OMA3_BOT_ULLLURLR_VMONS (see 4[4B]), OMA3_TOP_ULLLURLR_VMONS (see 4[6A]), OMB1_BOT_ULLLURLR_VMONS (see 2[4D]), OMB1_TOP_ULLLURLR_VMONS (see 2[6B]), OMB2_TOP_ULLLURLR_VMONS (see 3[6B]), OMB3_BOT_ULLLURLR_VMONS (see 4[4C]), OMB3_TOP_ULLLURLR_VMONS (see 4[6A]), OMCAB_H1V1H2V2_VMONS (see 5[6B]), OMCAB_H3V3H4V4_VMONS (see 5[6B])

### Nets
SUS_HAM6_300: C61.SCSI(ToADC) C62.SCSI(Output)
SUS_HAM6_310: C63.SCSI(ToADC) C64.SCSI(Output)
SUS_HAM6_320: C65.SCSI(ToADC) C66.SCSI(Output)
SUS_OBS_008: C61.D9M(IN13-16) ; port OBS_TOP_F1F2F3SD_VMONS
SUS_OBS_010: C61.D9M(IN17-20) ; port OBS_TOP_LFRTxxxx_VMONS
SUS_OM0_007: C61.D9M(IN1-4) ; port OM0_TOP_F1F2F3SD_VMONS
SUS_OM0_012: C61.D9M(IN5-8) ; port OM0_TOP_LFRTxxxx_VMONS
SUS_OM0_018: C61.D9M(IN9-12) ; port OM0_BOT_ULLLURLR_D_VMONS
SUS_OMA1_005: C63.D9M(IN17-20) ; port OMA1_TOP_ULLLURLR_VMONS
SUS_OMA1_103: C63.D9M(IN21-24) ; port OMA1_BOT_ULLLURLR_VMONS
SUS_OMB1_005: C63.D9M(IN25-28) ; port OMB1_TOP_ULLLURLR_VMONS
SUS_OMB1_103: C63.D9M(IN29-32) ; port OMB1_BOT_ULLLURLR_VMONS
NetC63_D9M: C63.D9M(IN1-4) ; port AM1_TOP_ULLLURLR_VMONS
NetC63_D9M: C63.D9M(IN5-8) ; port AM2_TOP_ULLLURLR_VMONS  [a separate net that carries the same name]
NetC63_D9M: C63.D9M(IN9-12) ; port OMCAB_H1V1H2V2_VMONS  [a separate net that carries the same name]
NetC63_D9M: C63.D9M(IN13-16) ; port OMCAB_H3V3H4V4_VMONS  [a separate net that carries the same name]
NetC65_D9M: C65.D9M(IN1-4) ; port OMA2_TOP_ULLLURLR_VMONS
NetC65_D9M: C65.D9M(IN5-8) ; port OMB2_TOP_ULLLURLR_VMONS  [a separate net that carries the same name]
NetC65_D9M: C65.D9M(IN9-12) ; port OM[A/B]2 BOT_FSFS_PSAMS_VMONS  [a separate net that carries the same name]
NetC65_D9M: C65.D9M(IN13-16) ; port OM[A/B]3 BOT_FSFS_PSAMS_VMONS  [a separate net that carries the same name]
NetC65_D9M: C65.D9M(IN17-20) ; port OMA3_TOP_ULLLURLR_VMONS  [a separate net that carries the same name]
NetC65_D9M: C65.D9M(IN21-24) ; port OMA3_BOT_ULLLURLR_VMONS  [a separate net that carries the same name]
NetC65_D9M: C65.D9M(IN25-28) ; port OMB3_TOP_ULLLURLR_VMONS  [a separate net that carries the same name]
NetC65_D9M: C65.D9M(IN29-32) ; port OMB3_BOT_ULLLURLR_VMONS  [a separate net that carries the same name]

Not connected (* = marked no-connect by the designer): C61 Conec-3(DC+/-18)*; C63 Conec-3(DC+/-18)*; C65 Conec-3(DC+/-18)*

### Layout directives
Length: 6ft; DCC: HPDB68 M/M: SUS_HAM6_300, SUS_HAM6_310, SUS_HAM6_320

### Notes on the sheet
- spare

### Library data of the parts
C61 C63 C65 = AA_9pinAll: ISC AA Chassis 9PinD; Serial: Sxxxxxxx
C62 C64 C66 = ADC-16: 16 Chan, 16 Bit ADC

## Sheet D2300379-v1_RACK_SUS_R7.SchDoc: FIELD RACK SUS-R7
size C; Engineer: L. Sanchez; Organization: LIGO Laboratory; Address1: California Institute of Technology; Address2: Massachusetts Institute of Technology; DocumentNumber: D2300379; Revision: v1; SheetNumber: 8; SheetTotal: 9
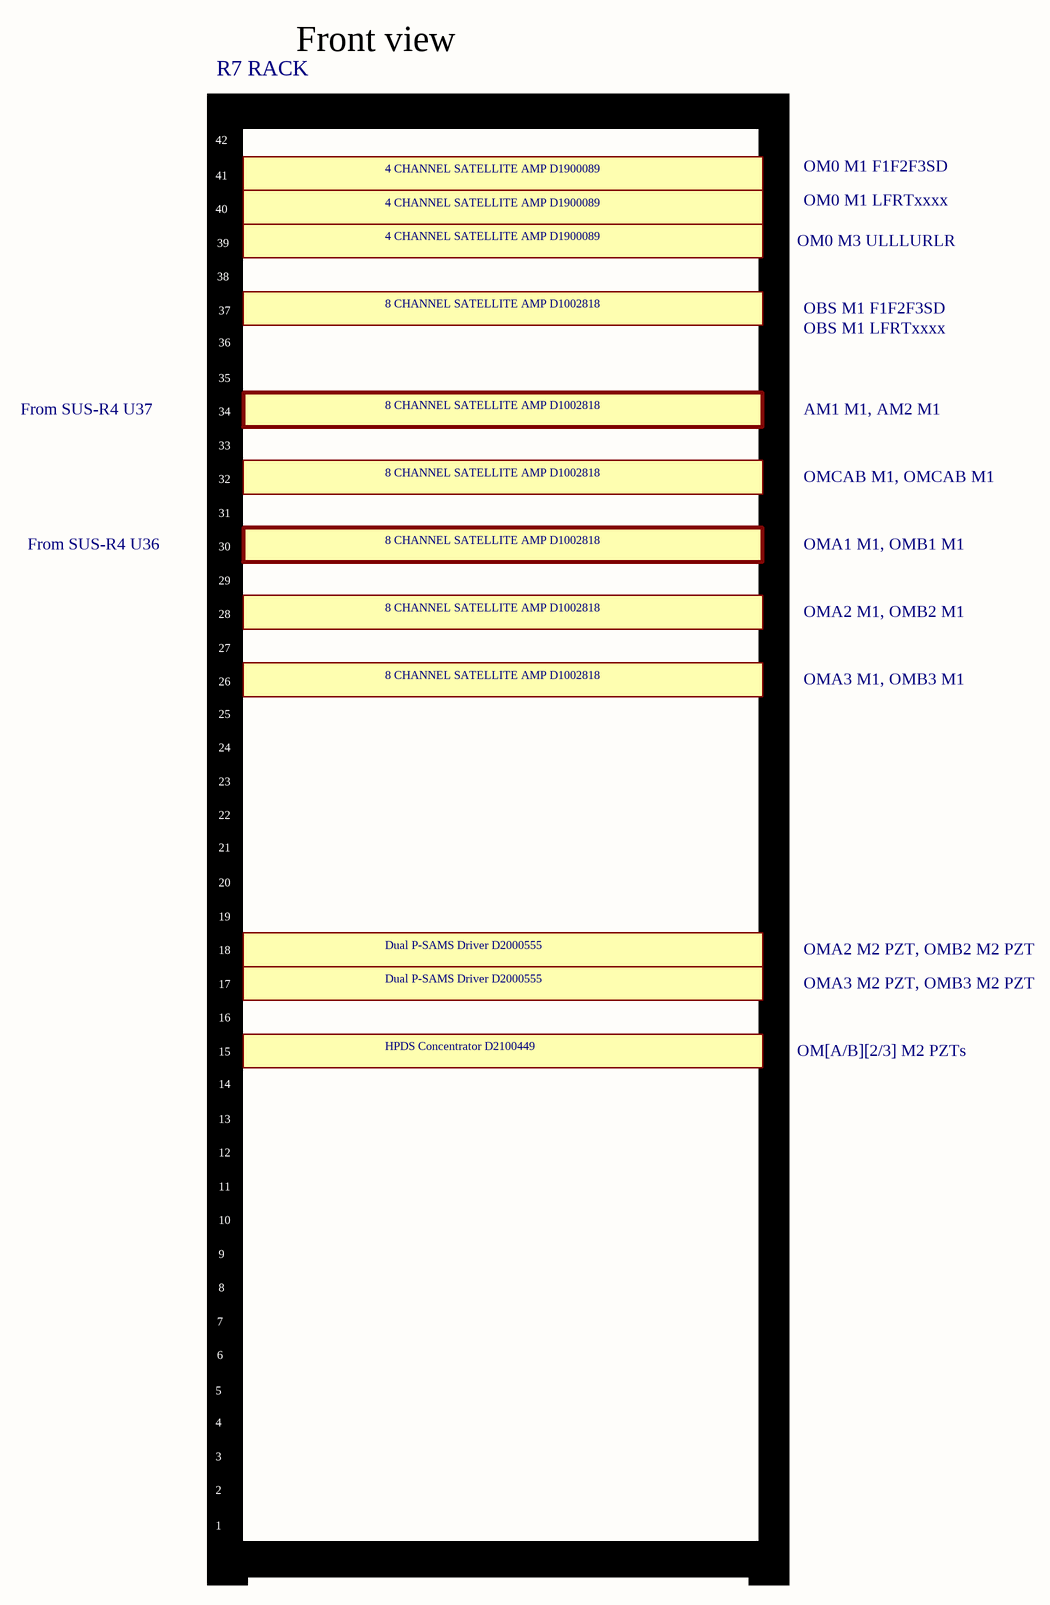
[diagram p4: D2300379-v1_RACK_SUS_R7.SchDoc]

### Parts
RackR2  1U  Rack 42 pos  (value not drawn)  (part A of 2)

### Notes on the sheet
- Front view
- R7 RACK
- 4 CHANNEL SATELLITE AMP D1900089
- OM0 M1 F1F2F3SD
- OM0 M3 ULLLURLR
- OM0 M1 LFRTxxxx
- 8 CHANNEL SATELLITE AMP D1002818
- OBS M1 F1F2F3SD
- OBS M1 LFRTxxxx
- From SUS-R4 U37
- AM1 M1, AM2 M1
- OMCAB M1, OMCAB M1
- From SUS-R4 U36
- OMA1 M1, OMB1 M1
- OMA2 M1, OMB2 M1
- OMA3 M1, OMB3 M1
- Dual P-SAMS Driver D2000555
- OMA3 M2 PZT, OMB3 M2 PZT
- OMA2 M2 PZT, OMB2 M2 PZT
- HPDS Concentrator D2100449
- OM[A/B][2/3] M2 PZTs

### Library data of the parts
RackR2 = RACK_42

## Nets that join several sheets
SUS_OBS_004: D2300379-v3_HAM6_OBS_OM0 (C6.D9F), D2300379-v1_SUS_HAM6_ADC_DAC (C55.D9M)
SUS_OBS_006: D2300379-v3_HAM6_OBS_OM0 (C6.D9F), D2300379-v1_SUS_HAM6_ADC_DAC (C55.D9M)
SUS_OBS_007: D2300379-v3_HAM6_OBS_OM0 (C?#1.D9M), D2300379-v1_SUS_HAM6_ADC_DAC (C48.D9F)
SUS_OBS_008: D2300379-v3_HAM6_OBS_OM0 (C?#1.D9F), D2300379-v1_SUSAUXH6_ADC_DAC (C61.D9M)
SUS_OBS_009: D2300379-v3_HAM6_OBS_OM0 (C?#2.D9M), D2300379-v1_SUS_HAM6_ADC_DAC (C48.D9F)
SUS_OBS_010: D2300379-v3_HAM6_OBS_OM0 (C?#2.D9F), D2300379-v1_SUSAUXH6_ADC_DAC (C61.D9M)
SUS_OM0_005: D2300379-v3_HAM6_OBS_OM0 (C?#3.D9F), D2300379-v1_SUS_HAM6_ADC_DAC (C49.D9M)
SUS_OM0_006: D2300379-v3_HAM6_OBS_OM0 (C?#3.D9M), D2300379-v1_SUS_HAM6_ADC_DAC (C48.D9F)
SUS_OM0_007: D2300379-v3_HAM6_OBS_OM0 (C?#3.D9F), D2300379-v1_SUSAUXH6_ADC_DAC (C61.D9M)
SUS_OM0_010: D2300379-v3_HAM6_OBS_OM0 (C?#4.D9F), D2300379-v1_SUS_HAM6_ADC_DAC (C49.D9M)
SUS_OM0_011: D2300379-v3_HAM6_OBS_OM0 (C?#4.D9M), D2300379-v1_SUS_HAM6_ADC_DAC (C48.D9F)
SUS_OM0_012: D2300379-v3_HAM6_OBS_OM0 (C?#4.D9F), D2300379-v1_SUSAUXH6_ADC_DAC (C61.D9M)
SUS_OM0_016: D2300379-v3_HAM6_OBS_OM0 (C?#5.D9M), D2300379-v1_SUS_HAM6_ADC_DAC (C58.D9F)
SUS_OM0_017: D2300379-v3_HAM6_OBS_OM0 (C?#5.D9F), D2300379-v1_SUS_HAM6_ADC_DAC (C49.D9M)
SUS_OM0_018: D2300379-v3_HAM6_OBS_OM0 (C?#5.D9F), D2300379-v1_SUSAUXH6_ADC_DAC (C61.D9M)
SUS_OMA1_003: D2300379-v3_HAM6_OMA1_OMB1 (C126.D9F), D2300379-v1_SUS_HAM6_ADC_DAC (C55.D9M)
SUS_OMA1_004: D2300379-v3_HAM6_OMA1_OMB1 (C125.D9M), D2300379-v1_SUS_HAM6_ADC_DAC (C54.D9F)
SUS_OMA1_005: D2300379-v3_HAM6_OMA1_OMB1 (C125.D9F), D2300379-v1_SUSAUXH6_ADC_DAC (C63.D9M)
SUS_OMA1_102: D2300379-v3_HAM6_OMA1_OMB1 (C?#12.D9M), D2300379-v1_SUS_HAM6_ADC_DAC (C54.D9F)
SUS_OMA1_103: D2300379-v3_HAM6_OMA1_OMB1 (C?#12.D9F), D2300379-v1_SUSAUXH6_ADC_DAC (C63.D9M)
SUS_OMB1_003: D2300379-v3_HAM6_OMA1_OMB1 (C126.D9F), D2300379-v1_SUS_HAM6_ADC_DAC (C55.D9M)
SUS_OMB1_004: D2300379-v3_HAM6_OMA1_OMB1 (C131.D9M), D2300379-v1_SUS_HAM6_ADC_DAC (C54.D9F)
SUS_OMB1_005: D2300379-v3_HAM6_OMA1_OMB1 (C131.D9F), D2300379-v1_SUSAUXH6_ADC_DAC (C63.D9M)
SUS_OMB1_102: D2300379-v3_HAM6_OMA1_OMB1 (C?#15.D9M), D2300379-v1_SUS_HAM6_ADC_DAC (C54.D9F)
SUS_OMB1_103: D2300379-v3_HAM6_OMA1_OMB1 (C?#15.D9F), D2300379-v1_SUSAUXH6_ADC_DAC (C63.D9M)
